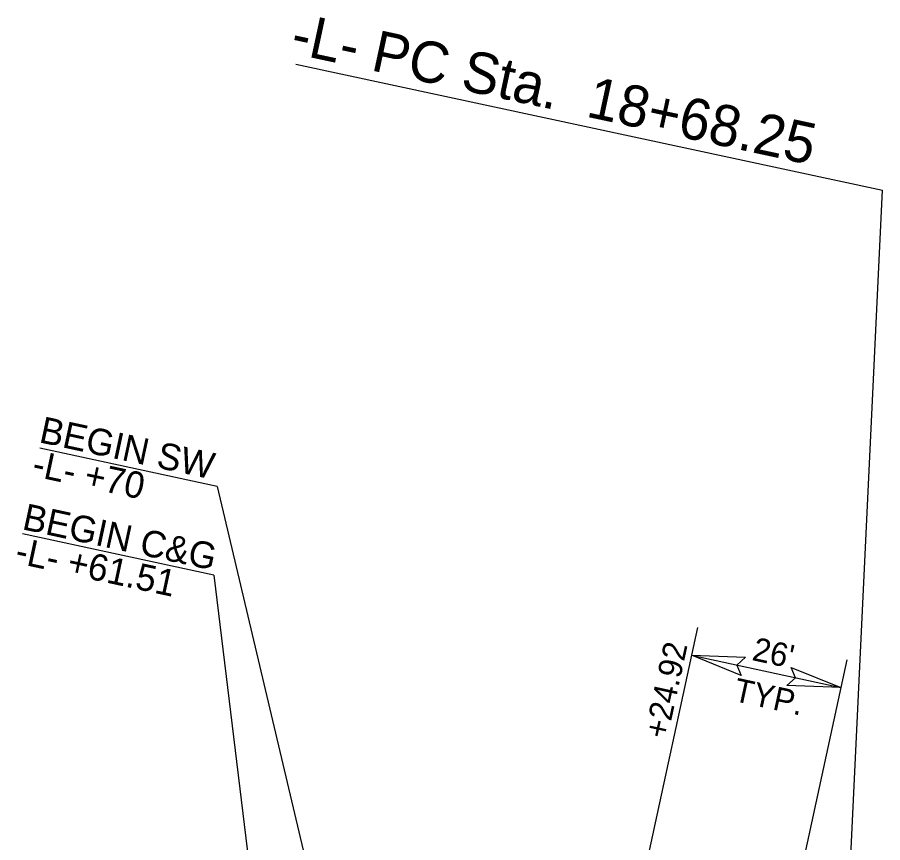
# Model space of a CAD drawing. Extents: x 1762196 to 1766326, y 709922 to 713142.
# Drawn here: x 1762906.7 to 1763053.9, y 712642.7 to 712783 of the extents above; entities that cross this region are included whole.
import ezdxf

# ---------------------------------------------------------------- set-up
doc = ezdxf.new("R2010")
doc.units = 0
for name, color, linetype in [('Prop Dimension', 7, 'Continuous'), ('Prop Horizontal Alignment Station Label', 7, 'Continuous'), ('Prop Superelevation Label', 7, 'Continuous'), ('Prop Terminator CELL', 7, 'Continuous')]:
    doc.layers.add(name, color=color, linetype=linetype)

msp = doc.modelspace()

# ---------------------------------------------------------------- linework, layer by layer
at = {"layer": 'Prop Dimension'}
for p, q in [((1762940.71, 712703.26), (1762910.5, 712709.76)), ((1762940.71, 712703.26), (1762956.72, 712635.5)), ((1762940.09, 712688.18), (1762907.58, 712695.17)), ((1762940.09, 712688.18), (1762947.08, 712631.1))]:
    msp.add_line(p, q, dxfattribs=at)
at = {"layer": 'Prop Horizontal Alignment Station Label'}
for p in [(1762954.09, 712775.08), (1763045.74, 712582.42)]:
    msp.add_line(p, (1763053.9, 712753.61), dxfattribs=at)
at = {"layer": 'Prop Superelevation Label'}
for p, q in [((1763022.41, 712679.27), (1763008.59, 712615.55)), ((1763021.38, 712674.55), (1763046.79, 712669.04)), ((1763047.82, 712673.76), (1763034, 712610.04))]:
    msp.add_line(p, q, dxfattribs=at)
at = {"layer": 'Prop Terminator CELL'}
for points in [[(1763029.85, 712671.13), (1763021.38, 712674.55), (1763030.57, 712674.2), (1763029.1, 712672.88)], [(1763038.33, 712672.46), (1763046.79, 712669.04), (1763037.61, 712669.39), (1763039.07, 712670.71)]]:
    msp.add_lwpolyline(points, close=True, dxfattribs=at)

# ---------------------------------------------------------------- texts
at = {"layer": 'Prop Dimension'}
for s, p in [('BEGIN SW', (1762910.22, 712710.79)), ('-L- +70', (1762908.99, 712705.07)), ('BEGIN C&G', (1762907.34, 712696)), ('-L- +61.51', (1762906.11, 712690.28))]:
    msp.add_text(s, height=4.5, rotation=347.8639, dxfattribs=at).set_placement(p)
at = {"layer": 'Prop Horizontal Alignment Station Label'}
msp.add_text('-L- PC Sta.  18+68.25', height=7, rotation=347.8638, dxfattribs=at).set_placement((1762952.91, 712777))
at = {"layer": 'Prop Superelevation Label'}
for s, rotation, p in [("26'", 347.7598, (1763031.51, 712673.75)), ('+24.92', 77.7598, (1763017.23, 712660.16)), ('TYP.', 347.7598, (1763028.33, 712666.81))]:
    msp.add_text(s, height=4, rotation=rotation, dxfattribs=at).set_placement(p)

doc.saveas('drawing.dxf')
